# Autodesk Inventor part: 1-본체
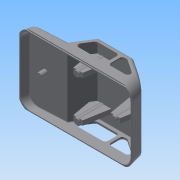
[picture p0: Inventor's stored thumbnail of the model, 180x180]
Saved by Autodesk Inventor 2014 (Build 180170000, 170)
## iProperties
Created: 2015-05
Part Number: 1-본체
Material: Generic
Document SubType Name: Modeling
Designer: Administrator
Density: 1 g/cm^3
Appearance: Default
Author: Administrator
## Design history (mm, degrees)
sketch "스케치1"
  geometry: L1 (-61, 0)-(61, 0); L2 (61, 11)-(57.412, 13.392); L3 (-58.588, 9)-(-19, 11.075); L4 (-6.549, 31)-(-19, 11.075); L5 (-61, 0)-(-58.588, 9); L6 (57.412, 13.392)-(61, 0); L7 (-6.549, 31)-(31, 31); L8 (61, 0)-(61, 13.212); L9 (57.412, 13.392)-(31, 31); 2 further points
  constraints: 18 end point, 1 coincident, 1 horizontal, 1 midpoint, 1 parallel, 1 perpendicular, 1 point on line
  dimensions: "d0" = 122 distance of L1.start L1.end; "d4" = 31 distance from line of L1 L7.end; "d9" = 9 vertical distance of L1.start L3.start; "d19" = 3 deg angle of L1 L3; "d21" = 125 deg angle of L3 L4; "d22" = 105 deg angle of L1 L5; "d23" = 105 deg angle of L1 L6; "d37" = 30 horizontal distance of L1.end L7.end; "d38" = 42 horizontal distance of L3.end L1.start; "d41" = 20 vertical distance of L7.end L2.start; "d42" = 31.74272 distance of L2.end L7.end
extrude "돌출1" new body sketch "스케치1" distance "d24" = 76; taper "d25" = 0 deg
fillet "모깎기1" dims "d138" = 12
fillet "모깎기2" dims "d139" = 3
feature "쉘1" dims "d26" = 2
sketch "스케치2"
  geometry: L1 (31, 31)-(-6.549, 31) reference; L2 (-61, 0)-(61, 0) reference; L3 (57.412, 13.392)-(31, 31) reference; L4 (-6.549, 31)-(-19, 11.075) reference; L5 (30.242, 25.496)-(43.742, 16.496); L6 (28.578, 26)-(26.986, 26); L7 (42.078, 11)-(26.986, 11); L8 (23.986, 14)-(23.986, 23); L9 (17.849, 11)-(-7.739, 11); L10 (-10.283, 15.59)-(-4.659, 24.59); L11 (-2.115, 26)-(17.849, 26); L12 (20.849, 23)-(20.849, 14); A1 r 3 centre (-2.115, 23) between (-2.115, 26) and (-4.659, 24.59); A2 r 3 centre (-7.739, 14) between (-10.283, 15.59) and (-7.739, 11); A3 r 3 centre (17.849, 23) between (20.849, 23) and (17.849, 26); A4 r 3 centre (17.849, 14) between (17.849, 11) and (20.849, 14); A5 r 3 centre (26.986, 23) between (26.986, 26) and (23.986, 23); A6 r 3 centre (26.986, 14) between (23.986, 14) and (26.986, 11); A7 r 3 centre (28.578, 23) between (30.242, 25.496) and (28.578, 26); A8 r 3 centre (42.078, 14) between (42.078, 11) and (43.742, 16.496); 6 further points
  constraints: 16 end point, 16 point on circle, 16 tangent, 10 point on line, 8 centre point, 7 equal radius, 5 parallel, 3 perpendicular
  dimensions: "d64" = 5 distance between parallel lines of L3 L5; "d65" = 5 distance between parallel lines of L1 L6; "d66" = 15 distance between parallel lines of L6 L7; "d67" = 28 distance of point (51.986, 11) point (23.986, 11); "d68" = 34 distance of point (20.849, 11) point (-13.151, 11); "d69" = 5 distance between parallel lines of L10 L4; "d70" = 15 distance from line of L9 point (-3.778, 26); "d71" = 5 distance between parallel lines of L11 L1; "d72" = 3 radius of A1
extrude "돌출2" cut sketch "스케치2" stored distance "d44" = 10; taper "d45" = 0 deg
sketch "스케치4"
  geometry: L1 (0, 76)-(0, 0) reference; L2 (28.121, 25)-(8.121, 25); L3 (8.121, 25)-(8.121, 51); L4 (8.121, 51)-(28.121, 51); L5 (28.121, 51)-(28.121, 25); L6 (28.121, 25)-(8.121, 51); L7 (8.121, 25)-(28.121, 51); L8 (-2.879, 76)-(-2.879, 0) reference; 4 further points
  constraints: 12 end point, 4 midpoint, 2 parallel, 1 horizontal, 1 horizontal alignment, 1 perpendicular
  dimensions: "d48" = 20 distance of L3.end L4.end; "d49" = 26 distance of L2.end L3.end; "d50" = 11 distance between parallel lines of L3 L8
extrude "돌출3" join sketch "스케치4" distance "d51" = 5; taper "d52" = 0 deg
sketch "스케치6"
  geometry: L1 (0, 0)-(122, 0) reference; L2 (122, 0)-(122, 76) reference; L3 (0, 76)-(122, 76) reference; L4 (0, 0)-(0, 76) reference; L5 (121, 75)-(121, 1); L6 (121, 1)-(1, 1); L7 (1, 1)-(1, 75); L8 (1, 75)-(121, 75); 1 further point
  constraints: 8 end point, 3 other
  dimensions: "d55" = 1 distance between parallel lines of L8 L3
extrude "돌출4" cut sketch "스케치6" distance "d56" = 1; taper "d57" = 0 deg
node "작업 평면8"
sketch "스케치5"
  geometry: L1 (0, 0)-(0, 22) reference; L2 (16, 0)-(0, 0) reference; C1 r 3 at (8, 11); 3 further points
  constraints: 2 midpoint, 1 centre point, 1 horizontal alignment, 1 vertical alignment
  dimensions: "d54" = 6 diameter of C1
extrude "돌출5" join sketch "스케치5" stored distance "d58" = 1; taper "d59" = 0 deg
node "작업 평면3"
sketch "스케치11"
  geometry: L1 (121.732, 64)-(121.732, 12) reference; L2 (121, 7.283)-(121, 68.717) reference; C1 r 3 at (100.732, 38); 6 further points
  constraints: 1 centre point, 1 horizontal alignment, 1 midpoint
  dimensions: "d82" = 6 diameter of C1; "d83" = 21 distance from line of C1.centre L1
extrude "돌출9" join sketch "스케치11" stored distance "d84" = 1; taper "d85" = 0 deg
sketch "스케치8"
  geometry: L1 (66.173, 62)-(66.173, 10) reference; L2 (66.173, 36)-(-59.707, 36); C1 r 3 at (5.173, 14); C2 r 3 at (5.173, 58); C3 r 3 at (45.173, 36) reference; 4 further points; 1 other entity
  constraints: 2 centre point, 2 end point, 1 equal radius, 1 horizontal, 1 midpoint, 1 vertical alignment, 2 other
  dimensions: "d73" = 6 diameter of C2; "d74" = 61 distance from line of C2.centre L1; "d75" = 44 distance of C1.centre C2.centre
extrude "돌출7" join sketch "스케치8" stored distance "d76" = 1; taper "d77" = 0 deg
node "작업 평면1"
sketch "스케치9"
  geometry: L1 (55.675, 12.146)-(30.394, 29) reference; L2 (36.732, 1)-(36.732, 24.775) reference; L3 (42.732, 1)-(42.732, 20.775) reference; L4 (30.394, 29)-(-5.441, 29) reference; L5 (42.732, 1)-(42.802, 3); L6 (36.732, 1)-(36.662, 3); L7 (42.732, 1)-(36.732, 1) reference; L8 (39.732, 1)-(39.732, 22.775); L9 (39.732, 3)-(44.732, 3); L10 (44.732, 3)-(47.326, 17.712); L11 (53.542, 0)-(-53.542, 0) reference; L12 (-48.309, 1)-(48.309, 1) reference; L13 (39.732, 3)-(34.732, 3); L14 (34.732, 3)-(30.148, 29); 5 further points
  constraints: 14 end point, 6 point on line, 2 perpendicular, 1 equal length, 1 midpoint, 1 parallel, 2 other
  dimensions: "d92" = 4 deg angle of L5 L6; "d102" = 2 distance from line of L9.end L12; "d103" = 20 deg angle of L10 L14; "d104" = 10 distance of L9.end L13.end
extrude "돌출10" join sketch "스케치9" stored distance "d99" = 5; taper "d100" = 0 deg
node "작업 평면4"
node "작업 평면6"
sketch "스케치13"
  geometry: L1 (-3.268, 29)-(-3.268, 1) reference; L2 (2.732, 29)-(2.732, 1) reference; L3 (2.732, 1)-(-3.268, 1) reference; L4 (-0.268, 1)-(-0.268, 34.635); L5 (2.732, 1)-(2.802, 3); L6 (-3.268, 1)-(-3.338, 3); L7 (2.732, 3)-(4.732, 3); L8 (30.394, 29)-(-5.441, 29) reference; L9 (4.732, 3)-(9.317, 29); L10 (-3.268, 3)-(-5.268, 3); L11 (-5.441, 29)-(-17.856, 9.132) reference; L12 (-5.268, 3)-(-8.882, 23.494); L13 (2.732, 3)-(1.465, 3); L14 (1.465, 3)-(1.465, 29); L15 (-3.268, 3)-(-2.151, 3); L16 (-2.151, 3)-(-2.151, 29); 1 further point
  constraints: 22 end point, 8 point on line, 4 perpendicular, 2 parallel, 1 collinear, 1 equal length, 1 midpoint, 2 other
  dimensions: "d127" = 4 deg angle of L5 L6; "d128" = 20 deg angle of L9 L12; "d129" = 2 distance from line of L3 L7.end; "d130" = 10 distance of L7.end L10.end; "d133" = 1.1168 distance of L10.start L15.end; "d134" = 1.26688 distance of L7.start L13.end; "d135" = 5.63458 distance from line of L4.end L8
extrude "돌출12" join sketch "스케치13" stored distance "d131" = 5; taper "d132" = 0 deg
fillet "모깎기3" dims "d140" = 3
fillet "모깎기4" dims "d141" = 3
node "솔리드1"
mirror "대칭1"
other parameters: "d105" = -20.5, "d126" = -22
